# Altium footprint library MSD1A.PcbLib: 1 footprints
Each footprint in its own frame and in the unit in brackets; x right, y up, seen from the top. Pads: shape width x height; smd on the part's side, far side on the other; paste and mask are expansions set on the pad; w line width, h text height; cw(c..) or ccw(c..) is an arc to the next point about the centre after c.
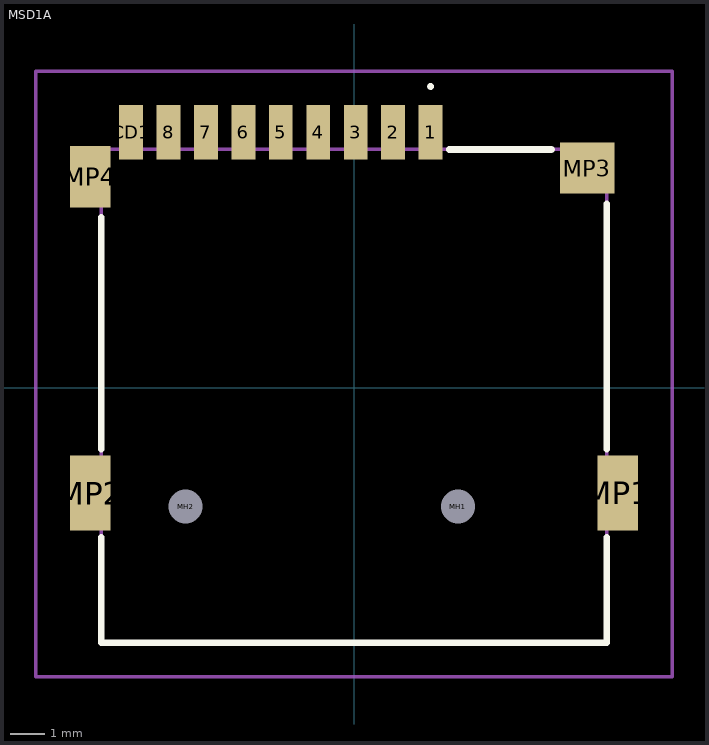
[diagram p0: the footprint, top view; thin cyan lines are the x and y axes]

## MSD1A [mm]
pads (15):
  rect 0.7x1.6 smd: 1(2.25,7.5) 2(1.15,7.5) 3(0.05,7.5) 4(-1.05,7.5) 5(-2.15,7.5) 6(-3.25,7.5) 7(-4.35,7.5) 8(-5.45,7.5) CD1(-6.55,7.5)
  round 0.5 hole 1 unplated: MH1(3.05,-3.5) MH2(-4.95,-3.5)
  rect 1.2x2.2 smd: MP1(7.75,-3.1) MP2(-7.75,-3.1)
  rect 1.6x1.5 smd: MP3(6.85,6.45)
  rect 1.2x1.8 smd: MP4(-7.75,6.2)
Top Overlay:
  lines w0.1: 2.25,8.8 cw(c2.25,8.85) 2.25,8.9 ; 2.25,8.8 2.25,8.8 ; 2.25,8.8 ccw(c2.25,8.85) 2.25,8.9 ; 2.25,8.9 2.25,8.9
  lines w0.2: -7.425,-4.4 -7.425,-7.5 7.425,-7.5 7.425,-4.4 ; -7.425,-1.8 -7.425,5 ; 2.8,7 5.8,7 ; 7.425,-1.8 7.425,5.4
Mechanical 15:
  lines w0.1: -7.425,-7.5 7.425,-7.5 7.425,7 -7.425,7 -7.425,-7.5
Mechanical 20:
  lines w0.1: -9.35,-8.5 9.35,-8.5 9.35,9.3 -9.35,9.3 -9.35,-8.5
